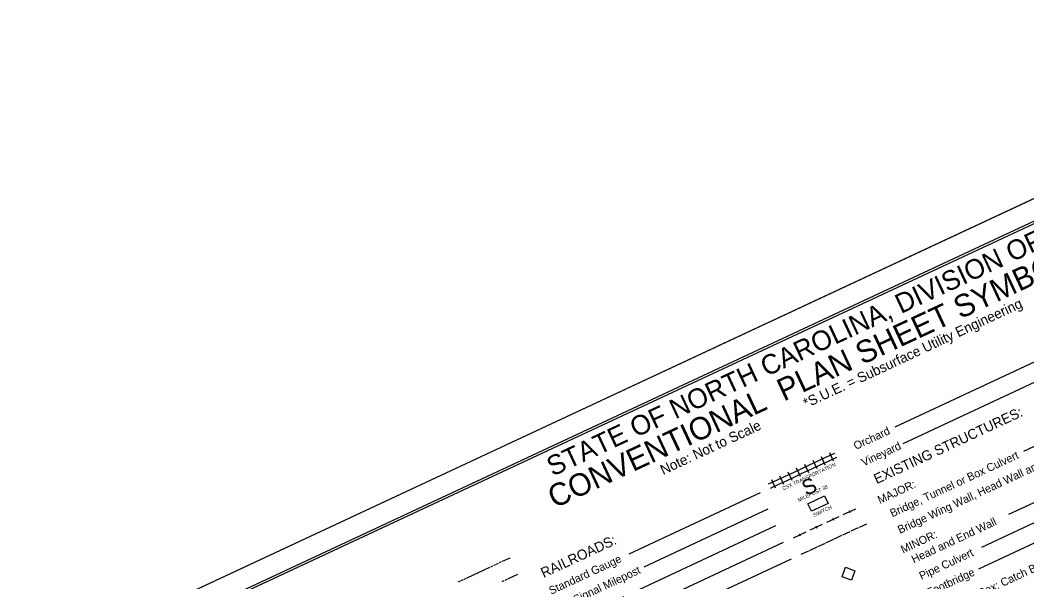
# Model space of a CAD drawing. Extents: x 2322304 to 2324295, y 918925 to 920634.
# Drawn here: x 2322304 to 2323404, y 920020 to 920634 of the extents above; entities that cross this region are included whole.
import ezdxf

# ---------------------------------------------------------------- set-up
doc = ezdxf.new("R2010")
doc.units = 0
for name, color, linetype in [('Default', 7, 'Continuous'), ('Sheet Cutting Line CELL', 7, 'Continuous'), ('Sheet Plot Border Inside CELL', 7, 'Continuous'), ('Sheet Plot Border Outside CELL', 7, 'Continuous'), ('Sheet Symbology CELL', 7, 'Continuous')]:
    doc.layers.add(name, color=color, linetype=linetype)

msp = doc.modelspace()

# ---------------------------------------------------------------- linework, layer by layer
at = {"layer": 'Default'}
msp.add_lwpolyline([(2323202.2, 920025.6), (2323205.9, 920036), (2323216.3, 920032.2), (2323212.6, 920021.8)], close=True, dxfattribs=at)
at = {"layer": 'Sheet Cutting Line CELL'}
msp.add_line((2323829.9, 920634.1), (2322303.9, 919921.9), dxfattribs=at)
at = {"layer": 'Sheet Plot Border Inside CELL'}
msp.add_lwpolyline([(2322771.4, 918950.9), (2324281.5, 919655.7), (2323835.3, 920611.8), (2322325.2, 919907)], close=True, dxfattribs=at)
at = {"layer": 'Sheet Plot Border Outside CELL'}
msp.add_lwpolyline([(2322769.1, 918925.1), (2324295.1, 919637.3), (2323829.9, 920634.1), (2322303.9, 919921.9)], close=True, dxfattribs=at)
at = {"layer": 'Sheet Symbology CELL'}
for p, q in [((2323445.7, 920275.8), (2323260, 920189.1)), ((2323454.2, 920257.7), (2323268.5, 920171)), ((2323477.1, 920198.3), (2323400.6, 920162.6)), ((2323176.2, 920152.5), (2323185.3, 920156.7)), ((2323183.9, 920147.8), (2323179.7, 920156.8)), ((2323185.3, 920156.7), (2323194.4, 920160.9)), ((2323187.4, 920152.2), (2323196.5, 920156.4)), ((2323193, 920152), (2323188.8, 920161.1)), ((2323149.1, 920139.8), (2323158.1, 920144)), ((2323156.8, 920135.1), (2323152.5, 920144.2)), ((2323158.1, 920144), (2323167.2, 920148.2)), ((2323160.2, 920139.5), (2323169.3, 920143.7)), ((2323165.8, 920139.3), (2323161.6, 920148.4)), ((2323167.2, 920148.2), (2323176.2, 920152.5)), ((2323169.3, 920143.7), (2323178.4, 920147.9)), ((2323174.9, 920143.5), (2323170.7, 920152.6)), ((2323178.4, 920147.9), (2323187.4, 920152.2)), ((2323500.6, 920147.9), (2323384.3, 920093.7)), ((2323130.9, 920131.3), (2323140, 920135.5)), ((2323138.6, 920126.6), (2323134.4, 920135.7)), ((2323140, 920135.5), (2323149.1, 920139.8)), ((2323142.1, 920131), (2323151.2, 920135.2)), ((2323147.7, 920130.9), (2323143.5, 920139.9)), ((2323151.2, 920135.2), (2323160.2, 920139.5)), ((2323121.9, 920127.1), (2323130.9, 920131.3)), ((2323124, 920122.6), (2323133.1, 920126.8)), ((2323129.6, 920122.4), (2323125.4, 920131.5)), ((2323133.1, 920126.8), (2323142.1, 920131)), ((2323509.1, 920129.8), (2323354.8, 920057.8)), ((2323112.7, 920117.5), (2322969.1, 920050.5)), ((2323517.5, 920111.7), (2323351.3, 920034.1)), ((2323121.1, 920099.4), (2322985.6, 920036.2)), ((2323203.6, 920093.8), (2323217.2, 920100.1)), ((2323185.5, 920085.3), (2323199.1, 920091.7)), ((2323191.8, 920089.6), (2323192.8, 920087.4)), ((2323209.9, 920098.1), (2323211, 920095.8)), ((2323129.6, 920081.3), (2322934.8, 919990.4)), ((2323167.4, 920076.9), (2323181, 920083.2)), ((2323173.7, 920081.2), (2323174.7, 920078.9)), ((2323212.1, 920075.7), (2323220.2, 920079.5)), ((2323221.2, 920079.9), (2323229.3, 920083.7)), ((2323149.3, 920068.4), (2323162.9, 920074.7)), ((2323155.5, 920072.7), (2323156.6, 920070.4)), ((2323184.9, 920063), (2323193.1, 920066.8)), ((2323194, 920067.2), (2323202.1, 920071)), ((2323203, 920071.4), (2323211.2, 920075.2)), ((2323138, 920063.2), (2322987.5, 919992.9)), ((2323166.8, 920054.5), (2323174.9, 920058.3)), ((2323175.8, 920058.7), (2323184, 920062.5)), ((2322831, 920042.6), (2322839.4, 920046.5)), ((2323146.5, 920045), (2322995.9, 919974.8)), ((2323146.5, 920045), (2322995.9, 919974.8)), ((2323157.7, 920050.3), (2323165.9, 920054.1)), ((2322792.5, 920024.6), (2322817.4, 920036.3)), ((2322818.3, 920036.7), (2322820.6, 920037.7)), ((2322821.5, 920038.2), (2322823.7, 920039.2)), ((2322824.7, 920039.6), (2322826.9, 920040.7)), ((2322827.8, 920041.1), (2322830.1, 920042.2)), ((2322786.1, 920021.7), (2322788.4, 920022.7)), ((2322789.3, 920023.2), (2322791.6, 920024.2)), ((2322833.9, 920021.9), (2322836.2, 920023)), ((2322837.1, 920023.4), (2322847.9, 920028.4)), ((2322783, 920020.2), (2322785.2, 920021.3)), ((2322830.7, 920020.4), (2322833, 920021.5))]:
    msp.add_line(p, q, dxfattribs=at)
for points in [[(2323825.1, 920604.2), (2322465.8, 919969.8), (2322909.4, 919019.3), (2324268.7, 919653.7)], [(2323165, 920105.5), (2323183.2, 920114), (2323187, 920105.7), (2323168.9, 920097.3)]]:
    msp.add_lwpolyline(points, close=True, dxfattribs=at)

# ---------------------------------------------------------------- texts
for s, height, p in [('STATE OF NORTH CAROLINA, DIVISION OF HIGHWAYS', 21.419, (2322885.9, 920135.1)), ('CONVENTIONAL  PLAN SHEET SYMBOLS', 24.48, (2322888, 920100.1)), ('*S.U.E. = Subsurface Utility Engineering', 11, (2323163, 920209.7)), ('EXISTING STRUCTURES:', 11, (2323240.1, 920126.8)), ('Note: Not to Scale', 11, (2323006.7, 920136.8)), ('Orchard', 8.75, (2323217.3, 920164.2)), ('Vineyard', 8.75, (2323225.8, 920146.1)), ('Bridge Wing Wall, Head Wall and End Wall', 8.75, (2323265.5, 920072.5)), ('Bridge, Tunnel or Box Culvert', 8.75, (2323257.1, 920090.6)), ('CSX TRANSPORTATION', 4, (2323138, 920120)), ('S', 16.5, (2323163.1, 920113.9)), ('MILEPOST 35', 4, (2323155, 920107.5)), ('MAJOR:', 8.75, (2323243.6, 920105.1)), ('SWITCH', 4, (2323171.8, 920091)), ('Head and End Wall', 8.75, (2323280.6, 920040.2)), ('RAILROADS:', 11, (2322876.1, 920024.2)), ('MINOR:', 8.75, (2323268.9, 920051)), ('Drainage Box: Catch Basin, DI or JB', 8.75, (2323307.8, 919981.9)), ('Pipe Culvert', 8.75, (2323289, 920022.1)), ('Standard Gauge', 8.75, (2322884.3, 920005.9)), ('RR Signal Milepost', 8.75, (2322892.7, 919987.8)), ('Footbridge', 8.75, (2323297.5, 920004))]:
    msp.add_text(s, height=height, rotation=25.0187, dxfattribs=at).set_placement(p)

doc.saveas('drawing.dxf')
